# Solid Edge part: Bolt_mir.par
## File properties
Author: Sarvanan
Template: Sync Iso Part.par
Last saved by: Sarvanan
Revision: 2
Application: Solid Edge
Username: Sarvanan
Accuracy: 0.990
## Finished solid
Body 1: solid body, 12 faces, 22 edges, 12 vertices.
  Faces by surface: plane 7, spun 4, cylinder 1
  Edges by curve: line 8, circle 7, intersection 7
Bounding box of the edges (mm; curved faces can reach further): 24.000 x 24.000 x 104.000, from (0, -21.6929, 0) to (24, 2.3071, 104).
Cylindrical faces by radius (mm): R6 x1
Planar faces by outward normal: +x 1, +y 1, +z 2, -x 1, -y 1, -z 1
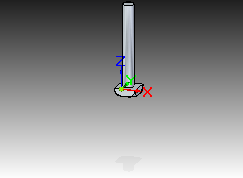
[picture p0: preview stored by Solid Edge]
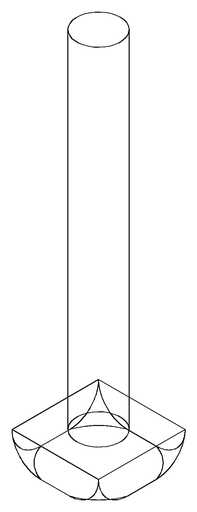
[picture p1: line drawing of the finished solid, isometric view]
